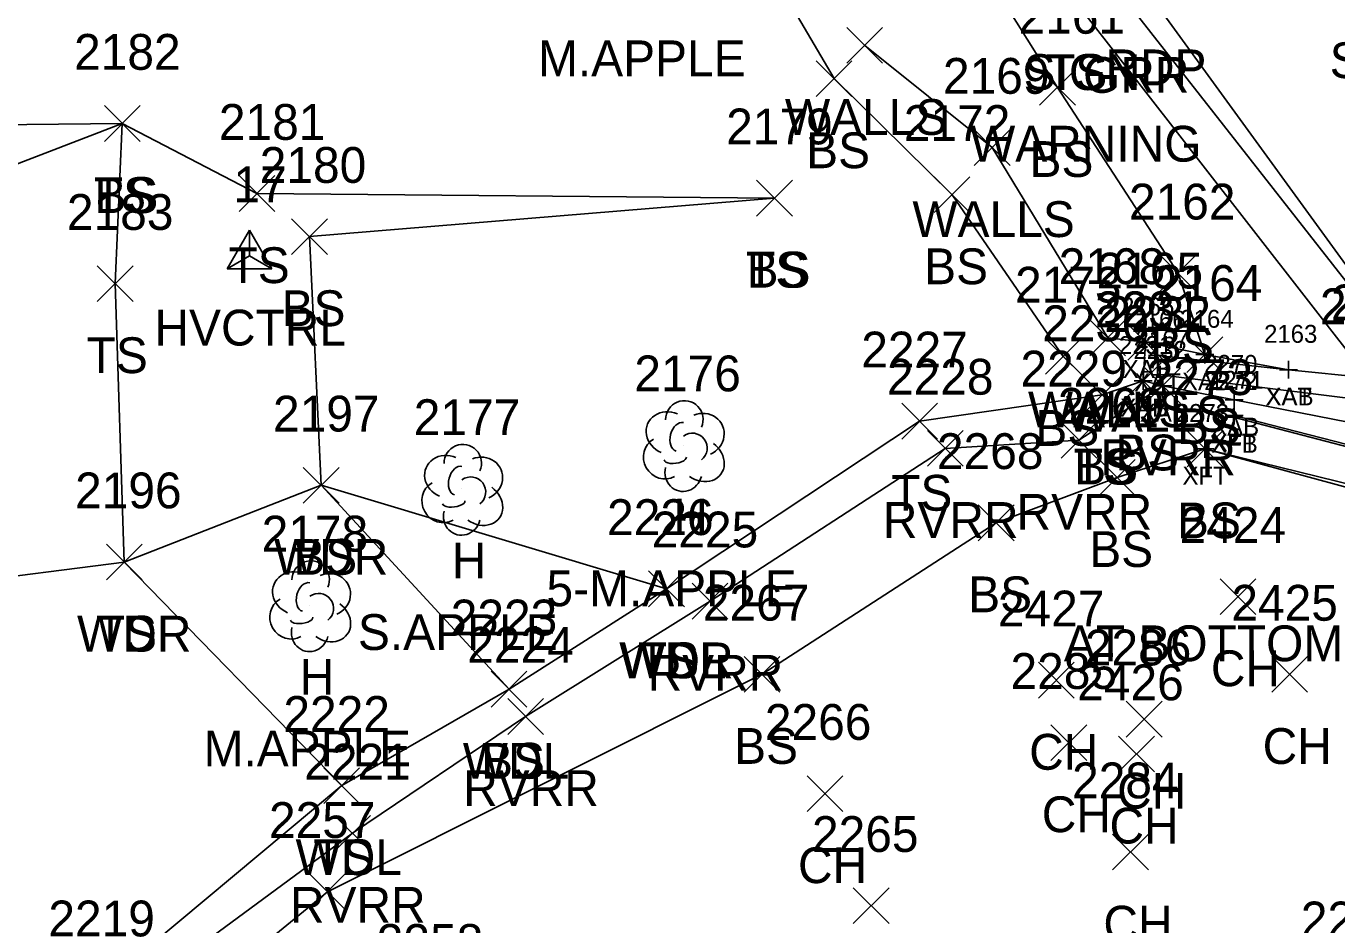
# Model space of a CAD drawing. Extents: x 1501299 to 1502485, y 381423 to 383765.
# Drawn here: x 1501524.4 to 1501597.6, y 383274.3 to 383324.5 of the extents above; entities that cross this region are included whole.
import ezdxf

# ---------------------------------------------------------------- set-up
doc = ezdxf.new("R2010")
doc.units = 0
for name, color, linetype in [('B_A', 7, 'Continuous'), ('B_I', 7, 'Continuous'), ('B_TIC', 7, 'Continuous'), ('BFT', 7, 'Continuous'), ('BSUBM', 7, 'Continuous'), ('C_A', 7, 'Continuous'), ('C_I', 7, 'Continuous'), ('CPSM', 7, 'Continuous'), ('L_A', 7, 'Continuous'), ('L_C', 7, 'Continuous'), ('L_I', 7, 'Continuous'), ('L_TIC', 7, 'Continuous'), ('LAWA', 7, 'Continuous'), ('LAWE', 7, 'Continuous'), ('LELB', 7, 'Continuous'), ('LTD', 7, 'Continuous'), ('LWS', 7, 'Continuous'), ('P_A', 7, 'Continuous'), ('PET', 7, 'Continuous'), ('R_A', 7, 'Continuous'), ('R_C', 7, 'Continuous'), ('RGR', 7, 'Continuous'), ('S_A', 7, 'Continuous'), ('S_C', 7, 'Continuous')]:
    doc.layers.add(name, color=color, linetype=linetype)

msp = doc.modelspace()

# ---------------------------------------------------------------- linework, layer by layer
at = {"layer": 'B_TIC'}
for p, q in [((1501586.944, 383306.811), (1501587.019, 383306.811)), ((1501587.603, 383306.071), (1501587.679, 383306.071)), ((1501590.255, 383306.118), (1501590.33, 383306.118)), ((1501587.752, 383304.989), (1501587.827, 383304.989)), ((1501587.752, 383304.989), (1501587.827, 383304.989)), ((1501594.93, 383305.277), (1501595.006, 383305.277)), ((1501594.93, 383305.277), (1501595.006, 383305.277)), ((1501586.807, 383304.65), (1501586.883, 383304.65)), ((1501587.902, 383304.381), (1501587.978, 383304.381)), ((1501591.889, 383303.599), (1501591.964, 383303.599)), ((1501591.849, 383302.634), (1501591.925, 383302.634)), ((1501591.896, 383302.71), (1501591.972, 383302.71)), ((1501590.261, 383300.858), (1501590.337, 383300.858))]:
    msp.add_line(p, q, dxfattribs=at)
for points in [[(1501586.94, 383306.311), (1501586.94, 383307.311)], [(1501586.44, 383306.811), (1501587.44, 383306.811)], [(1501587.6, 383305.571), (1501587.6, 383306.571)], [(1501590.251, 383305.618), (1501590.251, 383306.618)], [(1501587.1, 383306.071), (1501588.1, 383306.071)], [(1501587.749, 383304.489), (1501587.749, 383305.489)], [(1501587.749, 383304.489), (1501587.749, 383305.489)], [(1501589.751, 383306.118), (1501590.751, 383306.118)], [(1501594.927, 383304.777), (1501594.927, 383305.777)], [(1501594.927, 383304.777), (1501594.927, 383305.777)], [(1501586.804, 383304.15), (1501586.804, 383305.15)], [(1501587.249, 383304.989), (1501588.249, 383304.989)], [(1501587.249, 383304.989), (1501588.249, 383304.989)], [(1501587.899, 383303.881), (1501587.899, 383304.881)], [(1501594.427, 383305.277), (1501595.427, 383305.277)], [(1501594.427, 383305.277), (1501595.427, 383305.277)], [(1501586.304, 383304.65), (1501587.304, 383304.65)], [(1501587.399, 383304.381), (1501588.399, 383304.381)], [(1501591.885, 383303.099), (1501591.885, 383304.099)], [(1501591.385, 383303.599), (1501592.385, 383303.599)], [(1501591.346, 383302.634), (1501592.346, 383302.634)], [(1501591.393, 383302.71), (1501592.393, 383302.71)], [(1501591.846, 383302.134), (1501591.846, 383303.134)], [(1501591.893, 383302.21), (1501591.893, 383303.21)], [(1501590.258, 383300.358), (1501590.258, 383301.358)], [(1501589.758, 383300.858), (1501590.758, 383300.858)]]:
    msp.add_lwpolyline(points, dxfattribs=at)
at = {"layer": 'BFT'}
for points in [[(1501591.846, 383302.634), (1501599.551, 383300.612), (1501608.842, 383308.268), (1501614.526, 383312.873), (1501621.52, 383318.346), (1501622.623, 383321.06)], [(1501591.893, 383302.71), (1501599.583, 383300.737), (1501608.715, 383308.273), (1501614.382, 383312.876), (1501621.268, 383318.583), (1501622.487, 383321.046)], [(1501590.258, 383300.858), (1501600.794, 383298.267), (1501604.985, 383301.7), (1501610.419, 383306.178), (1501616.429, 383311.032), (1501623.09, 383316.78), (1501624.747, 383320.366)]]:
    msp.add_lwpolyline(points, dxfattribs=at)
at = {"layer": 'BSUBM'}
for points in [[(1501594.927, 383305.277), (1501590.251, 383306.118), (1501586.94, 383306.811), (1501586.804, 383304.65), (1501587.899, 383304.381), (1501591.885, 383303.599), (1501600.149, 383301.969), (1501608.182, 383308.826), (1501613.853, 383313.607), (1501621.021, 383319.534)], [(1501599.37, 383304.818), (1501594.927, 383305.277), (1501587.6, 383306.071), (1501587.749, 383304.989)], [(1501599.37, 383304.818), (1501599.99, 383305.028), (1501600.409, 383304.217), (1501599.738, 383303.508), (1501587.749, 383304.989)]]:
    msp.add_lwpolyline(points, dxfattribs=at)
at = {"layer": 'CPSM'}
for p, q in [((1501535.641, 383310.904), (1501536.891, 383313.069)), ((1501538.141, 383310.904), (1501536.891, 383313.069)), ((1501536.891, 383311.626), (1501536.891, 383313.069)), ((1501535.641, 383310.904), (1501536.891, 383311.626)), ((1501536.891, 383311.626), (1501536.891, 383311.626)), ((1501536.891, 383311.626), (1501538.141, 383310.904)), ((1501535.641, 383310.904), (1501538.141, 383310.904))]:
    msp.add_line(p, q, dxfattribs=at)
at = {"layer": 'L_TIC'}
for points in [[(1501570.254, 383322.387), (1501572.254, 383324.387)], [(1501572.254, 383322.387), (1501570.254, 383324.387)], [(1501568.542, 383320.529), (1501570.542, 383322.529)], [(1501570.542, 383320.529), (1501568.542, 383322.529)], [(1501581.018, 383320.04), (1501583.018, 383322.04)], [(1501583.018, 383320.04), (1501581.018, 383322.04)], [(1501528.789, 383318.024), (1501530.789, 383320.024)], [(1501530.789, 383318.024), (1501528.789, 383320.024)], [(1501528.789, 383318.024), (1501530.789, 383320.024)], [(1501530.789, 383318.024), (1501528.789, 383320.024)], [(1501528.789, 383318.024), (1501530.789, 383320.024)], [(1501530.789, 383318.024), (1501528.789, 383320.024)], [(1501577.371, 383316.684), (1501579.371, 383318.684)], [(1501579.371, 383316.684), (1501577.371, 383318.684)], [(1501536.309, 383314.112), (1501538.309, 383316.112)], [(1501538.309, 383314.112), (1501536.309, 383316.112)], [(1501565.215, 383313.859), (1501567.215, 383315.859)], [(1501567.215, 383313.859), (1501565.215, 383315.859)], [(1501565.215, 383313.859), (1501567.215, 383315.859)], [(1501567.215, 383313.859), (1501565.215, 383315.859)], [(1501575.131, 383314.049), (1501577.131, 383316.049)], [(1501577.131, 383314.049), (1501575.131, 383316.049)], [(1501539.243, 383311.709), (1501541.243, 383313.709)], [(1501541.243, 383311.709), (1501539.243, 383313.709)], [(1501587.751, 383309.663), (1501589.751, 383311.663)], [(1501589.751, 383309.663), (1501587.751, 383311.663)], [(1501528.387, 383309.084), (1501530.387, 383311.084)], [(1501530.387, 383309.084), (1501528.387, 383311.084)], [(1501583.824, 383306.055), (1501585.824, 383308.055)], [(1501585.824, 383306.055), (1501583.824, 383308.055)], [(1501585.94, 383305.811), (1501587.94, 383307.811)], [(1501587.94, 383305.811), (1501585.94, 383307.811)], [(1501581.343, 383305.021), (1501583.343, 383307.021)], [(1501583.343, 383305.021), (1501581.343, 383307.021)], [(1501589.251, 383305.118), (1501591.251, 383307.118)], [(1501591.251, 383305.118), (1501589.251, 383307.118)], [(1501585.804, 383303.65), (1501587.804, 383305.65)], [(1501587.804, 383303.65), (1501585.804, 383305.65)], [(1501583.514, 383302.868), (1501585.514, 383304.868)], [(1501585.514, 383302.868), (1501583.514, 383304.868)], [(1501583.514, 383302.868), (1501585.514, 383304.868)], [(1501585.514, 383302.868), (1501583.514, 383304.868)], [(1501586.899, 383303.381), (1501588.899, 383305.381)], [(1501588.899, 383303.381), (1501586.899, 383305.381)], [(1501573.321, 383301.4), (1501575.321, 383303.4)], [(1501575.321, 383301.4), (1501573.321, 383303.4)], [(1501574.755, 383299.881), (1501576.755, 383301.881)], [(1501576.755, 383299.881), (1501574.755, 383301.881)], [(1501582.22, 383300.337), (1501584.22, 383302.337)], [(1501584.22, 383300.337), (1501582.22, 383302.337)], [(1501589.258, 383299.858), (1501591.258, 383301.858)], [(1501591.258, 383299.858), (1501589.258, 383301.858)], [(1501539.898, 383297.823), (1501541.898, 383299.823)], [(1501541.898, 383297.823), (1501539.898, 383299.823)], [(1501539.898, 383297.823), (1501541.898, 383299.823)], [(1501541.898, 383297.823), (1501539.898, 383299.823)], [(1501584.352, 383298.258), (1501586.352, 383300.258)], [(1501586.352, 383298.258), (1501584.352, 383300.258)], [(1501577.593, 383295.727), (1501579.593, 383297.727)], [(1501579.593, 383295.727), (1501577.593, 383297.727)], [(1501528.899, 383293.534), (1501530.899, 383295.534)], [(1501530.899, 383293.534), (1501528.899, 383295.534)], [(1501528.899, 383293.534), (1501530.899, 383295.534)], [(1501530.899, 383293.534), (1501528.899, 383295.534)], [(1501559.179, 383292.041), (1501561.179, 383294.041)], [(1501561.179, 383292.041), (1501559.179, 383294.041)], [(1501559.179, 383292.041), (1501561.179, 383294.041)], [(1501561.179, 383292.041), (1501559.179, 383294.041)], [(1501559.179, 383292.041), (1501561.179, 383294.041)], [(1501561.179, 383292.041), (1501559.179, 383294.041)], [(1501561.616, 383291.351), (1501563.616, 383293.351)], [(1501563.616, 383291.351), (1501561.616, 383293.351)], [(1501591.099, 383291.601), (1501593.099, 383293.601)], [(1501593.099, 383291.601), (1501591.099, 383293.601)], [(1501564.518, 383287.263), (1501566.518, 383289.263)], [(1501566.518, 383287.263), (1501564.518, 383289.263)], [(1501580.95, 383286.935), (1501582.95, 383288.935)], [(1501582.95, 383286.935), (1501580.95, 383288.935)], [(1501593.989, 383287.258), (1501595.989, 383289.258)], [(1501595.989, 383287.258), (1501593.989, 383289.258)], [(1501550.388, 383286.435), (1501552.388, 383288.435)], [(1501552.388, 383286.435), (1501550.388, 383288.435)], [(1501550.388, 383286.435), (1501552.388, 383288.435)], [(1501552.388, 383286.435), (1501550.388, 383288.435)], [(1501551.314, 383284.91), (1501553.314, 383286.91)], [(1501553.314, 383284.91), (1501551.314, 383286.91)], [(1501585.86, 383284.761), (1501587.86, 383286.761)], [(1501587.86, 383284.761), (1501585.86, 383286.761)], [(1501581.655, 383283.448), (1501583.655, 383285.448)], [(1501583.655, 383283.448), (1501581.655, 383285.448)], [(1501585.436, 383282.814), (1501587.436, 383284.814)], [(1501587.436, 383282.814), (1501585.436, 383284.814)], [(1501541.045, 383281.049), (1501543.045, 383283.049)], [(1501543.045, 383281.049), (1501541.045, 383283.049)], [(1501541.045, 383281.049), (1501543.045, 383283.049)], [(1501543.045, 383281.049), (1501541.045, 383283.049)], [(1501568.038, 383280.603), (1501570.038, 383282.603)], [(1501570.038, 383280.603), (1501568.038, 383282.603)], [(1501541.641, 383278.387), (1501543.641, 383280.387)], [(1501543.641, 383278.387), (1501541.641, 383280.387)], [(1501585.094, 383277.338), (1501587.094, 383279.338)], [(1501587.094, 383277.338), (1501585.094, 383279.338)], [(1501540.24, 383275.124), (1501542.24, 383277.124)], [(1501542.24, 383275.124), (1501540.24, 383277.124)], [(1501570.615, 383274.344), (1501572.615, 383276.344)], [(1501572.615, 383274.344), (1501570.615, 383276.344)]]:
    msp.add_lwpolyline(points, dxfattribs=at)
at = {"layer": 'LAWA'}
for points in [[(1501455.233, 383277.691), (1501474.969, 383286.067), (1501488.159, 383291.024), (1501505.298, 383294.675), (1501520.544, 383293.338), (1501529.899, 383294.534), (1501540.898, 383298.823), (1501560.179, 383293.041)], [(1501493.174, 383231.392), (1501501.487, 383246.568), (1501511.284, 383257.189), (1501519.659, 383268.85), (1501528.358, 383270.628), (1501542.045, 383282.049), (1501551.388, 383287.435), (1501560.179, 383293.041)]]:
    msp.add_lwpolyline(points, dxfattribs=at)
at = {"layer": 'LAWE'}
msp.add_lwpolyline([(1501495.635, 383230.141), (1501503.588, 383244.326), (1501512.252, 383255.731), (1501521.044, 383267.417), (1501528.783, 383269.178), (1501542.641, 383279.387), (1501552.314, 383285.91), (1501562.616, 383292.351), (1501575.755, 383300.881), (1501583.22, 383301.337), (1501587.899, 383304.381)], dxfattribs=at)
at = {"layer": 'LELB'}
for points in [[(1501514.863, 383348.169), (1501532.009, 383356.376), (1501551.241, 383360.865), (1501559.526, 383359.149), (1501577.64, 383333.828), (1501582.97, 383325.895), (1501599.37, 383304.818)], [(1501558.924, 383357.388), (1501555.653, 383354.535), (1501554.386, 383341.888), (1501563.091, 383332.538), (1501569.542, 383321.529), (1501576.131, 383315.049), (1501582.343, 383306.021), (1501584.514, 383303.868), (1501586.804, 383304.65)], [(1501558.924, 383357.388), (1501573.959, 383333.908), (1501582.018, 383321.04), (1501588.751, 383310.663), (1501590.251, 383306.118)], [(1501498.194, 383229.3), (1501506.162, 383243.777), (1501514.118, 383255.518), (1501521.598, 383264.924), (1501530.006, 383266.909), (1501541.24, 383276.124), (1501565.518, 383288.263), (1501578.593, 383296.727), (1501585.352, 383299.258), (1501590.258, 383300.858), (1501600.796, 383297.995), (1501605.166, 383301.398), (1501610.699, 383306.054), (1501616.468, 383310.93), (1501623.409, 383316.642), (1501624.747, 383320.366)], [(1501529.789, 383319.024), (1501508.471, 383318.793), (1501498.449, 383314.158), (1501488.159, 383291.024), (1501493.84, 383282.989), (1501477.762, 383276.802), (1501469.368, 383268.993), (1501481.005, 383249.166), (1501469.559, 383246.339)], [(1501529.789, 383319.024), (1501511.352, 383311.935), (1501505.298, 383294.675), (1501497.775, 383280.73), (1501480.605, 383270.063), (1501487.356, 383250.583), (1501481.065, 383239.917)], [(1501566.215, 383314.859), (1501537.309, 383315.112), (1501529.789, 383319.024), (1501529.387, 383310.084), (1501529.899, 383294.534), (1501542.045, 383282.049)], [(1501566.215, 383314.859), (1501540.243, 383312.709), (1501540.898, 383298.823), (1501551.388, 383287.435)], [(1501560.179, 383293.041), (1501574.321, 383302.4), (1501584.514, 383303.868)]]:
    msp.add_lwpolyline(points, dxfattribs=at)
at = {"layer": 'LTD'}
for p, q in [((1501561.132, 383301.067), (1501561.132, 383301.067)), ((1501561.132, 383301.067), (1501561.132, 383301.067)), ((1501548.759, 383298.623), (1501548.759, 383298.623)), ((1501548.759, 383298.623), (1501548.759, 383298.623)), ((1501540.264, 383292.122), (1501540.264, 383292.122)), ((1501540.264, 383292.122), (1501540.264, 383292.122))]:
    msp.add_line(p, q, dxfattribs=at)
for centre in [(1501561.179, 383302.501), (1501548.806, 383300.057), (1501540.311, 383293.556)]:
    msp.add_arc(centre, 1.047, 335.52715, 180.95627, dxfattribs=at)
for centre, major_axis, ratio, start_param, end_param in [((1501560.34, 383301.734), (1.21, -0.512), 0.895232, 1.570796, 4.712389), ((1501562.174, 383301.651), (-1.141, -0.483), 0.949671, 1.570796, 4.712389), ((1501560.924, 383301.526), (-0.208, -0.792), 0.645439, 3.141593, 6.283185), ((1501561.632, 383300.901), (-0.5, 0.667), 0.989748, 3.141593, 6.283185), ((1501560.049, 383300.359), (0.584, -1.042), 0.959034, 3.141593, 6.283185), ((1501562.132, 383300.234), (-1.09, 0.792), 0.841452, 1.570796, 4.712389), ((1501547.967, 383299.29), (1.21, -0.512), 0.895232, 1.570796, 4.712389), ((1501549.801, 383299.207), (-1.141, -0.483), 0.949671, 1.570796, 4.712389), ((1501560.674, 383300.317), (-0.625, -0.083), 0.423636, 0, 3.141593), ((1501548.551, 383299.081), (-0.208, -0.792), 0.645439, 3.141593, 6.283185), ((1501561.132, 383299.567), (0.265, 1.061), 0.942809, 1.570796, 4.712389), ((1501547.676, 383297.915), (0.584, -1.042), 0.959034, 3.141593, 6.283185), ((1501549.259, 383298.457), (-0.5, 0.667), 0.989748, 3.141593, 6.283185), ((1501549.759, 383297.79), (-1.09, 0.792), 0.841452, 1.570796, 4.712389), ((1501548.301, 383297.873), (-0.625, -0.083), 0.423636, 0, 3.141593), ((1501548.759, 383297.123), (0.265, 1.061), 0.942809, 1.570796, 4.712389), ((1501539.473, 383292.789), (1.21, -0.512), 0.895232, 1.570796, 4.712389), ((1501541.306, 383292.706), (-1.141, -0.483), 0.949671, 1.570796, 4.712389), ((1501540.056, 383292.58), (-0.208, -0.792), 0.645439, 3.141593, 6.283185), ((1501539.181, 383291.414), (0.584, -1.042), 0.959034, 3.141593, 6.283185), ((1501540.764, 383291.955), (-0.5, 0.667), 0.989748, 3.141593, 6.283185), ((1501541.264, 383291.289), (-1.09, 0.792), 0.841452, 1.570796, 4.712389), ((1501540.265, 383290.622), (0.265, 1.061), 0.942809, 1.570796, 4.712389), ((1501539.806, 383291.372), (-0.625, -0.083), 0.423636, 0, 3.141593)]:
    msp.add_ellipse(centre, major_axis=major_axis, ratio=ratio, start_param=start_param, end_param=end_param, dxfattribs=at)
at = {"layer": 'LWS'}
msp.add_lwpolyline([(1501586.94, 383306.811), (1501584.824, 383307.055), (1501578.371, 383317.684), (1501571.254, 383323.387)], dxfattribs=at)
at = {"layer": 'PET'}
msp.add_lwpolyline([(1501334.826, 383720.255), (1501358.007, 383682.468), (1501375.272, 383653.985), (1501391.807, 383626.284), (1501413.667, 383590.156), (1501441.928, 383545.301), (1501463.314, 383511.64), (1501483.045, 383481.713), (1501501.394, 383453.556), (1501521.788, 383422.955), (1501532.703, 383406.598), (1501560.323, 383365.298), (1501580.554, 383335.852), (1501587.206, 383326.159), (1501601.645, 383306.284)], dxfattribs=at)
at = {"layer": 'RGR'}
msp.add_lwpolyline([(1501577.64, 383333.828), (1501585.957, 383325.738), (1501601.432, 383306.001)], dxfattribs=at)

# ---------------------------------------------------------------- texts
at = {"layer": 'B_A'}
for s, p in [('XAB', (1501585.661, 383304.811)), ('XAT', (1501586.304, 383304.071)), ('XAB', (1501588.972, 383304.118)), ('XAT', (1501586.453, 383302.989)), ('XAT', (1501586.453, 383302.989)), ('XAT', (1501593.631, 383303.277)), ('XAB', (1501593.647, 383303.277)), ('XAB', (1501585.524, 383302.65)), ('XAB', (1501586.619, 383302.381)), ('XAB', (1501590.606, 383301.599)), ('XFB', (1501590.606, 383300.634)), ('XFT', (1501590.637, 383300.71)), ('XFT', (1501589.002, 383298.858))]:
    msp.add_text(s, height=1, dxfattribs=at).set_placement(p)
at = {"layer": 'B_I'}
for s, p in [('2165', (1501585.57, 383308.311)), ('2166', (1501586.202, 383307.571)), ('2164', (1501588.881, 383307.618)), ('2163', (1501593.557, 383306.777)), ('2163', (1501593.557, 383306.777)), ('2231', (1501585.457, 383306.15)), ('2167', (1501586.379, 383306.489)), ('2167', (1501586.379, 383306.489)), ('2232', (1501586.269, 383305.881)), ('2270', (1501590.212, 383305.099)), ('2272', (1501590.216, 383304.134)), ('2271', (1501590.546, 383304.21)), ('2273', (1501588.628, 383302.358))]:
    msp.add_text(s, height=1, dxfattribs=at).set_placement(p)
at = {"layer": 'C_A'}
msp.add_text('HVCTRL', height=2, dxfattribs=at).set_placement((1501531.584, 383306.626))
at = {"layer": 'C_I'}
msp.add_text('17', height=2, dxfattribs=at).set_placement((1501535.994, 383314.626))
at = {"layer": 'L_A'}
for s, p in [('TS', (1501581.38, 383320.895)), ('WALLS', (1501566.797, 383318.387)), ('BS', (1501567.983, 383316.529)), ('BS', (1501580.459, 383316.04)), ('TS', (1501528.199, 383314.024)), ('TS', (1501528.199, 383314.024)), ('BS', (1501528.23, 383314.024)), ('WALLS', (1501573.915, 383312.684)), ('TS', (1501535.719, 383310.112)), ('BS', (1501574.572, 383310.049)), ('TS', (1501564.625, 383309.859)), ('BS', (1501564.656, 383309.859)), ('BS', (1501538.684, 383307.709)), ('BS', (1501587.192, 383305.663)), ('TS', (1501527.796, 383305.084)), ('WALLS', (1501580.368, 383302.055)), ('WALLS', (1501582.484, 383301.811)), ('BS', (1501580.784, 383301.021)), ('BS', (1501588.692, 383301.118)), ('RVRR', (1501584.41, 383299.381)), ('BS', (1501585.245, 383299.65)), ('TS', (1501582.924, 383298.868)), ('BS', (1501582.955, 383298.868)), ('TS', (1501572.73, 383297.4)), ('RVRR', (1501579.732, 383296.337)), ('H', (1501560.565, 383296.067)), ('RVRR', (1501572.267, 383295.881)), ('BS', (1501588.699, 383295.858)), ('BS', (1501583.793, 383294.258)), ('WDR', (1501538.26, 383293.823)), ('BS', (1501539.339, 383293.823)), ('H', (1501548.192, 383293.623)), ('BS', (1501577.034, 383291.727)), ('TS', (1501528.309, 383289.534)), ('WDR', (1501527.261, 383289.534)), ('WDR', (1501557.541, 383288.041)), ('WDL', (1501557.596, 383288.041)), ('TS', (1501558.588, 383288.041)), ('RVRR', (1501559.128, 383287.351)), ('CH', (1501590.587, 383287.601)), ('H', (1501539.697, 383287.122)), ('BS', (1501563.959, 383283.263)), ('CH', (1501580.438, 383282.935)), ('CH', (1501593.478, 383283.258)), ('WDL', (1501548.806, 383282.435)), ('BS', (1501549.829, 383282.435)), ('RVRR', (1501548.826, 383280.91)), ('CH', (1501585.348, 383280.761)), ('CH', (1501581.144, 383279.448)), ('CH', (1501584.925, 383278.814)), ('WDL', (1501539.463, 383277.049)), ('TS', (1501540.455, 383277.049)), ('CH', (1501567.526, 383276.603)), ('RVRR', (1501539.153, 383274.387)), ('CH', (1501584.583, 383273.338))]:
    msp.add_text(s, height=2, dxfattribs=at).set_placement(p)
at = {"layer": 'L_C'}
for s, p in [('M.APPLE', (1501553.005, 383321.665)), ('5-M.APPLE', (1501553.479, 383292.067)), ('S.APPLE', (1501542.948, 383289.623)), ('AT BOTTOM OF FOOTING', (1501582.379, 383288.995)), ('M.APPLE', (1501534.327, 383283.122))]:
    msp.add_text(s, height=2, dxfattribs=at).set_placement(p)
at = {"layer": 'L_I'}
for s, p in [('2161', (1501579.845, 383324.04)), ('2182', (1501527.096, 383322.024)), ('2182', (1501527.096, 383322.024)), ('2182', (1501527.096, 383322.024)), ('2169', (1501575.624, 383320.684)), ('2181', (1501535.183, 383318.112)), ('2179', (1501563.515, 383317.859)), ('2179', (1501563.515, 383317.859)), ('2172', (1501573.438, 383318.049)), ('2180', (1501537.464, 383315.709)), ('2183', (1501526.694, 383313.084)), ('2162', (1501586.011, 383313.663)), ('2168', (1501582.084, 383310.055)), ('2165', (1501584.2, 383309.811)), ('2173', (1501579.65, 383309.021)), ('2164', (1501587.511, 383309.118)), ('2157', (1501596.677, 383307.818)), ('2158', (1501597.298, 383308.028)), ('2231', (1501584.111, 383307.65)), ('2232', (1501584.639, 383307.381)), ('2230', (1501581.168, 383306.868)), ('2230', (1501581.168, 383306.868)), ('2227', (1501571.061, 383305.4)), ('2229', (1501579.953, 383304.337)), ('2176', (1501558.384, 383304.067)), ('2228', (1501572.495, 383303.881)), ('2273', (1501586.998, 383303.858)), ('2269', (1501582.037, 383302.258)), ('2197', (1501538.205, 383301.823)), ('2197', (1501538.205, 383301.823)), ('2177', (1501546.066, 383301.623)), ('2268', (1501575.286, 383299.727)), ('2196', (1501527.151, 383297.534)), ('2196', (1501527.151, 383297.534)), ('2226', (1501556.864, 383296.041)), ('2226', (1501556.864, 383296.041)), ('2226', (1501556.864, 383296.041)), ('2424', (1501588.839, 383295.601)), ('2178', (1501537.572, 383295.122)), ('2225', (1501559.356, 383295.351)), ('2267', (1501562.211, 383291.263)), ('2425', (1501591.73, 383291.258)), ('2223', (1501548.129, 383290.435)), ('2223', (1501548.129, 383290.435)), ('2427', (1501578.69, 383290.935)), ('2224', (1501549.054, 383288.91)), ('2286', (1501583.545, 383288.761)), ('2285', (1501579.396, 383287.448)), ('2426', (1501583.122, 383286.814)), ('2222', (1501538.785, 383285.049)), ('2222', (1501538.785, 383285.049)), ('2266', (1501565.676, 383284.603)), ('2221', (1501539.948, 383282.387)), ('2284', (1501582.835, 383281.338)), ('2257', (1501537.98, 383279.124)), ('2265', (1501568.308, 383278.344)), ('2219', (1501525.657, 383273.628)), ('2283', (1501595.611, 383273.571)), ('2258', (1501543.999, 383272.316))]:
    msp.add_text(s, height=2, dxfattribs=at).set_placement(p)
at = {"layer": 'P_A'}
msp.add_text('RDP', height=2, dxfattribs=at).set_placement((1501584.694, 383321.159))
at = {"layer": 'R_A'}
msp.add_text('GRR', height=2, dxfattribs=at).set_placement((1501583.446, 383320.738))
at = {"layer": 'R_C'}
msp.add_text('SGRW/STEEL POST', height=2, dxfattribs=at).set_placement((1501597.223, 383321.56))
at = {"layer": 'S_A'}
msp.add_text('SIGN', height=2, dxfattribs=at).set_placement((1501580.128, 383320.895))
at = {"layer": 'S_C'}
msp.add_text('WARNING', height=2, dxfattribs=at).set_placement((1501577.136, 383316.895))

doc.saveas('drawing.dxf')
